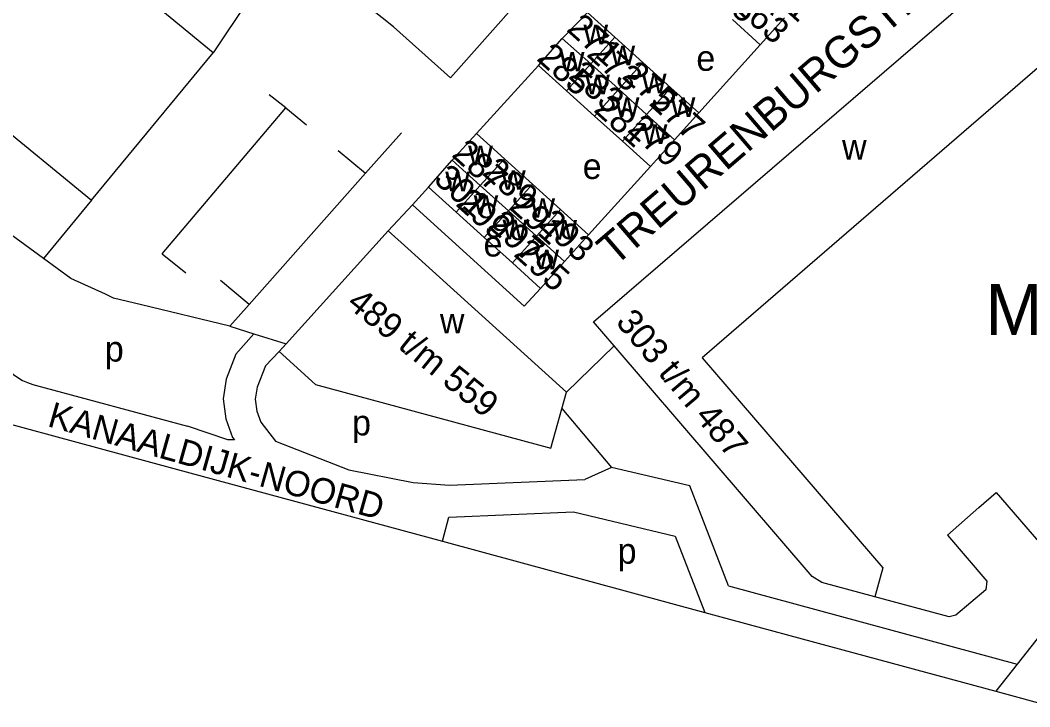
# Model space of a CAD drawing. Extents: x 161775 to 163181, y 382878 to 383925.
# Drawn here: x 162004.9 to 162163.6, y 383100.5 to 383208.3 of the extents above; entities that cross this region are included whole.
import ezdxf

# ---------------------------------------------------------------- set-up
doc = ezdxf.new("R2010")
doc.units = 0
for name, color, linetype in [('BLT_Basislijn', 7, 'Continuous'), ('BLT_Bebouwing', 7, 'Continuous'), ('BLT_Bebouwing_beschrifting', 7, 'Continuous'), ('BLT_Centroide', 7, 'Continuous'), ('BLT_Huisnummer', 7, 'Continuous'), ('BLT_Huisnummer_reeks', 7, 'Continuous'), ('BLT_Onderverdeling_panden', 7, 'Continuous'), ('BLT_Straatnaam', 7, 'Continuous'), ('BLT_Straatnaam_verkleind', 7, 'Continuous')]:
    doc.layers.add(name, color=color, linetype=linetype)

msp = doc.modelspace()

# ---------------------------------------------------------------- linework, layer by layer
at = {"layer": 'BLT_Basislijn'}
for p, q in [((162118.59, 383251.19), (162072.53, 383199.31)), ((162111.55, 383193.78), (162121.22, 383204.49)), ((162076.62, 383190.56), (162086.4, 383201.23)), ((162046.66, 383194.55), (162044.07, 383196.63)), ((162027.23, 383171.66), (162046.66, 383194.55)), ((162046.66, 383194.55), (162049.93, 383191.93)), ((162064.84, 383190.65), (162059.22, 383184.32)), ((162054.9, 383187.86), (162059.22, 383184.32)), ((162094.25, 383174.61), (162103.95, 383185.36)), ((162059.22, 383184.32), (162040.91, 383163.7)), ((162066.57, 383179.34), (162069.12, 383182.1)), ((162016.17, 383180.07), (162008.61, 383170.89)), ((162062.76, 383175.24), (162066.57, 383179.34)), ((162008.61, 383170.89), (162000.77, 383176.62)), ((162012.88, 383167.77), (162008.61, 383170.89)), ((162027.23, 383171.66), (162030.95, 383168.67)), ((162018.34, 383165.29), (162012.88, 383167.77)), ((162040.91, 383163.7), (162036.43, 383167.47)), ((162040.91, 383163.7), (162037.87, 383160.27)), ((162037.87, 383160.27), (162041.65, 383159.09)), ((162041.65, 383159.09), (162046.74, 383157.5)), ((162090.75, 383149.93), (162098.24, 383157.17)), ((162090.04, 383147.37), (162097.86, 383138.08)), ((162029.11, 383137.91), (162071.27, 383126.49)), ((162097.86, 383138.08), (162093.67, 383136.22)), ((162071.27, 383126.49), (162112.49, 383115.33)), ((162116.24, 383119.49), (162161.59, 383107.21)), ((162112.49, 383115.33), (162136.15, 383108.92)), ((162161.59, 383107.21), (162158.24, 383102.93))]:
    msp.add_line(p, q, dxfattribs=at)
for points in [[(161967.44, 383258.8), (161974.67, 383265.82), (162040.76, 383211.42), (162035.26, 383203.21)], [(162072.53, 383199.31), (162063.57, 383207.3), (162056.2, 383213.19), (162021.83, 383241.43), (162025.01, 383245.29)], [(162086.68, 383166.22), (162084.13, 383163.4), (162066.57, 383179.34)], [(162024.01, 383163.64), (162019.63, 383164.7), (162018.34, 383165.29)], [(162037.87, 383160.27), (162024.01, 383163.64)], [(162000.39, 383160.18), (162000.4, 383159.32), (162000.5, 383158.47), (162000.67, 383157.63), (162000.92, 383156.81), (162001.25, 383156.02), (162001.65, 383155.26), (162002.12, 383154.54), (162002.65, 383153.87), (162003.24, 383153.25), (162003.89, 383152.69), (162004.59, 383152.2), (162005.33, 383151.77), (162006.11, 383151.41), (162006.92, 383151.12), (162007.51, 383150.97), (162031.25, 383144.55)], [(162041.65, 383159.09), (162038.8, 383155.87), (162037.3, 383151.98), (162036.82, 383148.87), (162037.24, 383145.75), (162038.32, 383142.78), (162038.6, 383142.41), (162037.57, 383142.41), (162031.25, 383144.55)], [(162045.64, 383156.28), (162043.47, 383154.07), (162042.16, 383150.68), (162041.87, 383148.82), (162042.13, 383146.95), (162042.76, 383145.2), (162045.05, 383142.21)], [(161987.3, 383150.22), (161986.97, 383149.33), (162029.11, 383137.91)], [(162045.05, 383142.21), (162056.57, 383137.74), (162066.66, 383135.73), (162072.38, 383135.31), (162093.67, 383136.22)], [(162116.24, 383119.49), (162110.16, 383135.19), (162097.86, 383138.08)], [(162071.27, 383126.49), (162072.3, 383130.3), (162091.86, 383131.14)], [(162091.86, 383131.14), (162107.85, 383127.29), (162112.49, 383115.33)], [(162169.84, 383116.67), (162168.9, 383115.87), (162167.42, 383114.65), (162161.59, 383107.21)], [(162136.15, 383108.92), (162158.24, 383102.93)], [(162158.24, 383102.93), (162167.23, 383100.5)]]:
    msp.add_lwpolyline(points, dxfattribs=at)
at = {"layer": 'BLT_Bebouwing'}
for p, q in [((162035.26, 383203.21), (162010.9, 383223.27)), ((162090.1, 383205.49), (162094.09, 383209.53)), ((162094.09, 383209.53), (162098.38, 383205.66)), ((162121.22, 383204.49), (162125.03, 383208.71)), ((162116.84, 383208.47), (162121.22, 383204.49)), ((162086.4, 383201.23), (162090.1, 383205.49)), ((162098.38, 383205.66), (162102.77, 383201.7)), ((162016.17, 383180.07), (162035.26, 383203.21)), ((162086.4, 383201.23), (162090.79, 383197.26)), ((162102.77, 383201.7), (162107.16, 383197.73)), ((162111.55, 383193.78), (162107.16, 383197.73)), ((162090.79, 383197.26), (162095.17, 383193.29)), ((162095.17, 383193.29), (162099.56, 383189.33)), ((162107.75, 383189.57), (162111.55, 383193.78)), ((162072.81, 383186.35), (162076.62, 383190.56)), ((162076.62, 383190.56), (162081.03, 383186.57)), ((162099.56, 383189.33), (162103.95, 383185.36)), ((162103.95, 383185.36), (162107.75, 383189.57)), ((162081.03, 383186.57), (162085.44, 383182.58)), ((162069.12, 383182.1), (162072.81, 383186.35)), ((162069.12, 383182.1), (162073.44, 383178.19)), ((162085.44, 383182.58), (162089.85, 383178.59)), ((162094.25, 383174.61), (162089.85, 383178.59)), ((162073.44, 383178.19), (162077.85, 383174.2)), ((162062.76, 383175.24), (162046.74, 383157.5)), ((162077.85, 383174.2), (162082.27, 383170.21)), ((162090.46, 383170.42), (162094.25, 383174.61)), ((162082.27, 383170.21), (162086.68, 383166.22)), ((162086.68, 383166.22), (162090.46, 383170.42)), ((162046.74, 383157.5), (162045.64, 383156.28))]:
    msp.add_line(p, q, dxfattribs=at)
for points in [[(161951.97, 383232.39), (162000, 383193.28), (162016.17, 383180.07)], [(162098.24, 383157.17), (162094.99, 383160.95), (162158.66, 383215.71)], [(162062.76, 383175.24), (162065.83, 383172.46), (162090.75, 383149.93)], [(162139.22, 383117.78), (162130.87, 383120.02), (162129.36, 383120.96), (162098.24, 383157.17)], [(162045.64, 383156.28), (162051.36, 383151.12), (162088.31, 383141.12), (162090.75, 383149.93)], [(162155.57, 383131.79), (162158.27, 383134.16), (162168.59, 383122.2)], [(162155.57, 383131.79), (162150.61, 383127.44), (162156.83, 383120.23), (162156.63, 383118.86), (162151.92, 383114.89), (162150.88, 383114.65), (162139.22, 383117.78)]]:
    msp.add_lwpolyline(points, dxfattribs=at)
at = {"layer": 'BLT_Onderverdeling_panden'}
for p, q in [((162090.1, 383205.49), (162094.58, 383201.46)), ((162094.58, 383201.46), (162098.38, 383205.66)), ((162090.79, 383197.26), (162094.58, 383201.46)), ((162094.58, 383201.46), (162098.97, 383197.49)), ((162098.97, 383197.49), (162102.77, 383201.7)), ((162103.36, 383193.53), (162107.16, 383197.73)), ((162095.17, 383193.29), (162098.97, 383197.49)), ((162098.97, 383197.49), (162103.36, 383193.53)), ((162103.36, 383193.53), (162099.56, 383189.33)), ((162103.36, 383193.53), (162107.75, 383189.57)), ((162077.23, 383182.37), (162081.03, 383186.57)), ((162072.81, 383186.35), (162077.23, 383182.37)), ((162077.23, 383182.37), (162073.44, 383178.19)), ((162077.23, 383182.37), (162081.64, 383178.38)), ((162081.64, 383178.38), (162085.44, 383182.58)), ((162086.05, 383174.4), (162089.85, 383178.59)), ((162077.85, 383174.2), (162081.64, 383178.38)), ((162081.64, 383178.38), (162086.05, 383174.4)), ((162082.27, 383170.21), (162086.05, 383174.4)), ((162086.05, 383174.4), (162090.46, 383170.42))]:
    msp.add_line(p, q, dxfattribs=at)
msp.add_lwpolyline([(162208.44, 383177.2), (162178.19, 383212.41), (162112.09, 383155.29), (162140.45, 383122.3), (162139.22, 383117.78)], dxfattribs=at)

# ---------------------------------------------------------------- texts
at = {"layer": 'BLT_Bebouwing_beschrifting'}
msp.add_text('Museum', height=8, dxfattribs=at).set_placement((162156.6, 383158.92))
at = {"layer": 'BLT_Centroide'}
for s, p in [('w', (162093.44, 383204.54)), ('w', (162097.69, 383201.25)), ('w', (162089.74, 383200.29)), ('e', (162111.17, 383200.39)), ('w', (162093.72, 383196.72)), ('w', (162102.62, 383196.86)), ('w', (162098.37, 383193.15)), ('w', (162107.15, 383193.15)), ('w', (162102.76, 383188.9)), ('w', (162075.33, 383185.54)), ('w', (162134.06, 383186.44)), ('e', (162093.32, 383183.4)), ('w', (162071.73, 383181.46)), ('w', (162080.5, 383181.7)), ('w', (162076.19, 383177.78)), ('w', (162085.12, 383177.31)), ('w', (162080.73, 383173.94)), ('w', (162088.56, 383173.86)), ('e', (162077.74, 383171.22)), ('w', (162085.74, 383169.23)), ('w', (162070.88, 383159.14)), ('p', (162018.24, 383154.72)), ('p', (162057.08, 383143.13)), ('p', (162098.8, 383122.98))]:
    msp.add_text(s, height=4, dxfattribs=at).set_placement(p)
at = {"layer": 'BLT_Huisnummer'}
for s, p in [('265', (162112.02, 383213.6)), ('261', (162120.68, 383213.82)), ('263', (162116.84, 383210.34)), ('271', (162090.64, 383206.77)), ('285', (162085.92, 383202.17)), ('273', (162093.78, 383202.82)), ('283', (162090.92, 383199.38)), ('275', (162099.33, 383199.37)), ('281', (162094.9, 383194.11)), ('277', (162103.57, 383195.15)), ('279', (162100.17, 383190.96)), ('287', (162072.57, 383187.05)), ('289', (162077.39, 383184.2)), ('301', (162069.73, 383183.09)), ('299', (162073.21, 383179.34)), ('291', (162081.62, 383178.8)), ('297', (162078.3, 383175.89)), ('293', (162086.22, 383176.06)), ('295', (162082.32, 383171.43))]:
    msp.add_text(s, height=4, rotation=318, dxfattribs=at).set_placement(p)
at = {"layer": 'BLT_Huisnummer_reeks'}
for s, rotation, p in [('489 t/m 559', 321, (162056.05, 383163.5)), ('303 t/m 487', 310, (162098.37, 383160.85))]:
    msp.add_text(s, height=4, rotation=rotation, dxfattribs=at).set_placement(p)
at = {"layer": 'BLT_Straatnaam'}
msp.add_text('TREURENBURGSTRAAT', height=5, rotation=40.6265, dxfattribs=at).set_placement((162098.34, 383169.54))
at = {"layer": 'BLT_Straatnaam_verkleind'}
msp.add_text('KANAALDIJK-NOORD', height=4, rotation=344.2351, dxfattribs=at).set_placement((162009.08, 383144.6))

doc.saveas('drawing.dxf')
